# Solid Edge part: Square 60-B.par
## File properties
Title: Square 60 x 51 Cm
Author: DESYS
Template: Normal.par
Last saved by: PIM_1
Revision: 12
Application: Solid Edge
Tipo di contenuto documento: 0
Precisione: 0,990
Document Number: 8007/B
Revision: 0
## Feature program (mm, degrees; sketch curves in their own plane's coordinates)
sketch for "unnamed Protrusion 1" plane through (0, 0, 0) normal (0, 0, 1) x-axis (1, 0, 0)
  line (-300, -255) -> (300, -255)
  line (300, -255) -> (300, 255)
  line (300, 255) -> (-300, 255)
  line (-300, 255) -> (-300, -255)
extrude "unnamed Protrusion 1" add finite 160 along -normal
sketch for "ExtrudedCutout_1" plane through (0, -210, -80) normal (0, -1, 0) x-axis (1, 0, 0)
  arc centre (0, 283.125) radius 303.125 from (-225, 80) to (225, 80) ccw
extrude "ExtrudedCutout_1" cut finite 330 along -normal  Profile_Plane1_Distance = 45 mm
sketch for "ExtrudedCutout_3" plane through (0, 0, -160) normal (0, 0, -1) x-axis (1, 0, 0)
  line (-190, -230) -> (190, -230)
  line (190, -230) -> (190, -125)
  line (-190, -125) -> (190, -125)
  line (-190, -125) -> (-190, -230)
  dimension (linear) = 190
extrude "ExtrudedCutout_3" cut finite 145 along -normal
sketch for "ExtrudedCutout_4" plane through (0, 125, -87.5) normal (0, 1, 0) x-axis (1, 0, 0)
  line (195, 68.5) -> (183.2769, 10.0335)
  arc centre (177.394, 11.2131) radius 6 from (175.6376, 5.4759) to (183.2769, 10.0335) ccw
  arc centre (0, -568.2413) radius 600 from (-175.6376, 5.4759) to (175.6376, 5.4759) cw
  arc centre (-177.394, 11.2131) radius 6 from (-183.2769, 10.0335) to (-175.6376, 5.4759) ccw
  line (-183.2769, 10.0335) -> (-195, 68.5)
extrude "ExtrudedCutout_4" cut finite 265 along -normal
sketch for "unnamed Protrusion 2" plane through (0, -55, -160) normal (0, 0, -1) x-axis (1, 0, 0)
  circle centre (0, -70) radius 35
extrude "unnamed Protrusion 2" add through along -normal
sketch for "Foro_1" plane through (0, 10, -160) normal (0, 0, -1) x-axis (0, -1, 0)
hole "Foro_1" diameter 45 through
draft "Draft_1"  Angles1 = 10 deg
sketch for "Foro_2" plane through (0, 0, 0) normal (0, 0, 1) x-axis (0, -1, 0)
  hole centre (-185, 0) bore radius 17.5
hole "Foro_2" diameter 35 through
sketch for "unnamed Protrusion 3" plane through (0, 0, 0) normal (1, 0, 0) x-axis (0, 1, 0)
  line (143.4613, -129.2045) -> (166.4997, -7.8356)
  arc centre (123.8093, -125.4896) radius 20 from (124.756, -145.4672) to (143.4613, -129.2045) ccw
  line (124.756, -145.4672) -> (50, -154.9389)
extrude "unnamed Protrusion 3" add to key point symmetric
fillet "Rotondo_1" radius 5
fillet "Rotondo_2" radius 10
fillet "Rotondo_3" radius 2
fillet "Rotondo_10" radius 10
sketch for "Foro_3" plane through (0, 0, 0) normal (0, -1, 0) x-axis (1, 0, 0)
  hole centre (0, -25) bore radius 10
hole "Foro_3" diameter 20 finite
fillet "Rotondo_11" radius 5  Radii2 = 10 mm
fillet "Rotondo_12" radius 5
fillet "Rotondo_15" radius 5
fillet "Rotondo_17" radius 5
fillet "Rotondo_18" radius 10
fillet "Rotondo_19" radius 5
sketch for "unnamed Cutout 1" #1 plane through (0, 255, -82.5) normal (0, 1, 0) x-axis (-1, 0, 0)
sketch for "unnamed Cutout 1" #2 plane through (0, 255, -82.5) normal (0, 1, 0) x-axis (-1, 0, 0)
extrude "unnamed Cutout 1" cut through along -normal
sketch for "unnamed Cutout 2" plane through (0, 255, -82.5) normal (0, 1, 0) x-axis (-1, 0, 0)
extrude "unnamed Cutout 2" cut through along -normal
fillet "Rotondo_20" radius 5
fillet "Rotondo_21" radius 5
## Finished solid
Body 1: solid body, 153 faces, 350 edges, 198 vertices.
  Faces by surface: cylinder 71, plane 33, blend 24, sphere 16, torus 9
  Edges by curve: line 148, circle 119, ellipse 47, intersection 36
Bounding box of the edges (mm; curved faces can reach further): 600.000 x 510.000 x 160.000, from (-300, -255, -160) to (300, 255, 0).
Cylindrical faces by radius (mm): R5 x49, R6 x2, R10 x12, R17.5 x1, R20 x1, R22.5 x1, R35 x1, R60 x2, R303.125 x1, R600 x1
Toroidal faces (ring radius, tube radius in mm): R5 r5 x2, R15 r5 x2, R19.5 r2 x1, R30 r5 x1, R65 r5 x2, R610 r10 x1
Spherical faces by radius (mm): R5 x16
Planar faces by outward normal: +x 3, +y 3, +z 3, -x 3, -y 3, -z 7, oblique 11
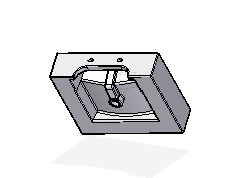
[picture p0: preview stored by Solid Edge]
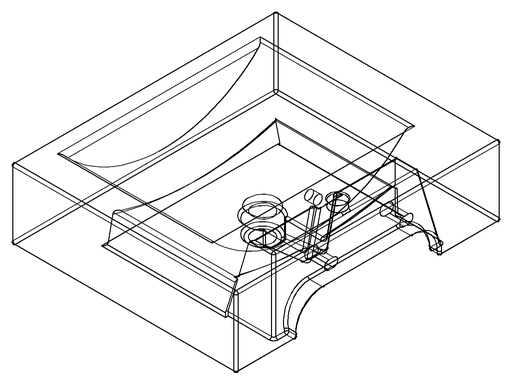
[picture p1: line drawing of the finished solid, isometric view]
